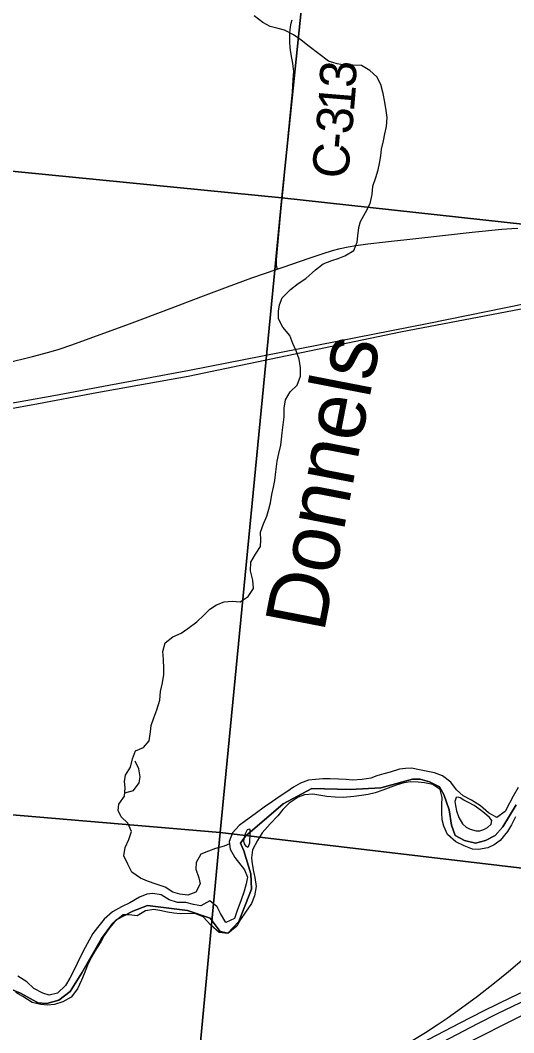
# Model space of a CAD drawing. Extents: x 831 to 1552, y 430 to 870.
# Drawn here: x 1297.11 to 1312.57, y 678.59 to 710.3 of the extents above; entities that cross this region are included whole.
import ezdxf

# ---------------------------------------------------------------- set-up
doc = ezdxf.new("R2010")
doc.units = 0
for name, color, linetype in [('GM_X_Corporation', 7, 'Continuous'), ('GM_X_County_Road', 7, 'Continuous'), ('GM_X_County_Road_Text', 7, 'Continuous'), ('GM_X_Interchange_Ramps', 7, 'Continuous'), ('GM_X_Interstate_Route', 7, 'Continuous'), ('GM_X_Major_River', 7, 'Continuous'), ('GM_X_Minor_River', 7, 'Continuous'), ('GM_X_Minor_River_Text', 7, 'Continuous'), ('GM_X_Rail_Line', 7, 'Continuous')]:
    doc.layers.add(name, color=color, linetype=linetype)

msp = doc.modelspace()

# ---------------------------------------------------------------- linework, layer by layer
at = {"layer": 'GM_X_Corporation'}
for points in [[(1287.469, 726.554), (1307.365, 724.655), (1305.299, 704.746), (1285.616, 706.68)], [(1307.365, 724.655), (1327.468, 722.912), (1325.539, 702.531), (1305.299, 704.746)], [(1305.299, 704.746), (1303.37, 684.858), (1283.584, 686.544), (1285.616, 706.68)], [(1305.299, 704.746), (1325.539, 702.531), (1323.531, 682.478), (1303.37, 684.858)], [(1283.584, 686.544), (1303.37, 684.858), (1301.464, 664.502), (1281.807, 666.237)], [(1303.37, 684.858), (1323.531, 682.478), (1321.541, 662.548), (1301.887, 664.457), (1301.464, 664.502)]]:
    msp.add_lwpolyline(points, close=True, dxfattribs=at)
for points in [[(1312.65, 685.727), (1312.224, 685.034), (1311.984, 684.768), (1311.69, 684.608), (1311.37, 684.528), (1311.023, 684.608), (1310.73, 684.768), (1310.623, 685.088), (1310.543, 685.568), (1310.383, 686.048), (1310.249, 686.288), (1309.929, 686.448), (1309.636, 686.528), (1309.396, 686.528), (1308.409, 686.262), (1307.449, 686.208), (1306.248, 686.235), (1305.341, 685.755), (1304.168, 684.742), (1304.007, 684.529), (1304.114, 684.289), (1304.328, 683.569), (1304.355, 683.089), (1303.954, 682.076), (1303.608, 681.702), (1303.368, 681.756), (1303.055, 682.179), (1302.347, 682.415), (1301.098, 682.568), (1300.638, 682.393), (1300.108, 682.128), (1300.004, 682.019), (1299.652, 681.539), (1299.039, 680.465), (1298.667, 679.874), (1298.316, 679.611), (1297.944, 679.502), (1297.659, 679.524), (1297.63, 679.54), (1297.111, 679.83), (1295.709, 680.4)], [(1295.709, 680.4), (1297.111, 679.83), (1297.63, 679.54), (1297.659, 679.524), (1297.944, 679.502), (1298.316, 679.611), (1298.667, 679.874), (1299.039, 680.465), (1299.652, 681.539), (1300.004, 682.019), (1300.108, 682.128), (1300.638, 682.393), (1301.098, 682.568), (1302.347, 682.415), (1303.055, 682.179), (1303.368, 681.756), (1303.608, 681.702), (1303.954, 682.076), (1304.355, 683.089), (1304.328, 683.569), (1304.114, 684.289), (1304.007, 684.529), (1304.168, 684.742), (1305.341, 685.755), (1306.248, 686.235), (1307.449, 686.208), (1308.409, 686.262), (1309.396, 686.528), (1309.636, 686.528), (1309.929, 686.448), (1310.249, 686.288), (1310.383, 686.048), (1310.543, 685.568), (1310.623, 685.088), (1310.73, 684.768), (1311.023, 684.608), (1311.37, 684.528), (1311.69, 684.608), (1311.984, 684.768), (1312.224, 685.034), (1312.65, 685.727)]]:
    msp.add_lwpolyline(points, dxfattribs=at)
at = {"layer": 'GM_X_County_Road'}
for points in [[(1305.159, 702.509), (1305.153, 702.543), (1305.138, 702.632), (1305.135, 702.671), (1305.141, 702.802), (1305.287, 704.41), (1305.365, 705.213), (1305.452, 706.14), (1305.636, 708.057), (1305.664, 708.429), (1305.673, 708.586), (1305.675, 708.711), (1305.671, 708.776), (1305.663, 708.854), (1305.648, 708.961), (1305.622, 709.114), (1305.59, 709.299), (1305.57, 709.448), (1305.557, 709.617), (1305.55, 709.768), (1305.551, 709.907), (1305.56, 709.992), (1305.577, 710.102), (1305.6, 710.211), (1305.625, 710.32)], [(1305.159, 702.509), (1305.345, 702.573), (1306.163, 702.854), (1306.596, 702.998), (1306.894, 703.089), (1307.135, 703.153), (1307.379, 703.207), (1307.625, 703.249), (1307.994, 703.3), (1308.55, 703.366), (1309.601, 703.482), (1311.27, 703.663), (1312.198, 703.759), (1312.508, 703.784), (1312.696, 703.791)], [(1292.633, 698.634), (1292.832, 698.659), (1293.002, 698.688), (1293.111, 698.71), (1293.836, 698.882), (1294.929, 699.15), (1295.727, 699.34), (1296.648, 699.564), (1297.492, 699.772), (1298.005, 699.907), (1298.324, 700.001), (1298.721, 700.132), (1300.531, 700.794), (1301.831, 701.285), (1302.769, 701.643), (1303.599, 701.948), (1304.36, 702.232), (1305.159, 702.509)]]:
    msp.add_lwpolyline(points, dxfattribs=at)
at = {"layer": 'GM_X_Interchange_Ramps'}
msp.add_lwpolyline([(1316.766, 684.819), (1316.253, 684.266), (1315.369, 683.31), (1314.816, 682.723), (1314.381, 682.282), (1313.979, 681.895), (1313.477, 681.432), (1312.968, 680.979), (1312.401, 680.496), (1311.97, 680.143), (1311.432, 679.723), (1310.935, 679.352), (1310.48, 679.028), (1310.172, 678.821), (1309.805, 678.588), (1309.008, 678.109), (1307.562, 677.263), (1306.957, 676.925), (1306.87, 676.872), (1306.781, 676.807), (1306.736, 676.769), (1306.693, 676.73), (1306.652, 676.687), (1306.577, 676.607)], dxfattribs=at)
at = {"layer": 'GM_X_Interstate_Route'}
for points in [[(1296.221, 671.1), (1298.795, 672.482), (1301.269, 673.783), (1303.737, 675.096), (1306.577, 676.607), (1306.973, 676.818), (1309.934, 678.396), (1310.869, 678.886), (1311.642, 679.283), (1312.478, 679.693), (1313.096, 679.984), (1313.775, 680.291), (1314.453, 680.589), (1314.514, 680.616), (1315.029, 680.832), (1315.72, 681.109), (1316.416, 681.372), (1317.469, 681.748), (1318.641, 682.161), (1319.931, 682.613), (1320.991, 682.995), (1322.52, 683.559), (1323.315, 683.849), (1323.468, 683.902)], [(1308.905, 677.534), (1309.028, 677.6), (1310.125, 678.184), (1311.445, 678.879), (1312.057, 679.186), (1312.786, 679.534), (1313.002, 679.632)]]:
    msp.add_lwpolyline(points, dxfattribs=at)
at = {"layer": 'GM_X_Major_River'}
for points in [[(1312.709, 686.272), (1312.551, 685.994), (1312.44, 685.776), (1312.305, 685.52), (1312.042, 685.329), (1311.779, 685.479), (1311.525, 685.69), (1311.247, 685.871), (1310.984, 686.006), (1310.776, 686.193), (1310.598, 686.433), (1310.337, 686.637), (1310.088, 686.733), (1309.83, 686.777), (1309.618, 686.827), (1309.368, 686.871), (1309.178, 686.86), (1308.987, 686.842), (1308.696, 686.749), (1308.497, 686.693), (1308.283, 686.637), (1308.091, 686.565), (1307.816, 686.518), (1307.519, 686.494), (1307.322, 686.521), (1307.079, 686.526), (1306.82, 686.54), (1306.584, 686.537), (1306.363, 686.519), (1306.135, 686.494), (1305.889, 686.401), (1305.666, 686.276), (1305.465, 686.136), (1305.218, 685.974), (1305.009, 685.834), (1304.747, 685.658), (1304.468, 685.443), (1304.166, 685.229), (1303.965, 685.082), (1303.762, 684.85), (1303.657, 684.579), (1303.682, 684.335), (1303.836, 684.081), (1304.132, 683.694), (1304.225, 683.456), (1304.19, 683.251), (1304.124, 683.017), (1304.018, 682.715), (1303.905, 682.421), (1303.816, 682.164), (1303.547, 682.041), (1303.386, 682.326), (1303.277, 682.534), (1303.045, 682.721), (1302.767, 682.56), (1302.54, 682.603)], [(1312.628, 685.353), (1312.5, 685.098), (1312.374, 684.888), (1312.147, 684.611), (1311.954, 684.471), (1311.754, 684.377), (1311.464, 684.33), (1311.274, 684.342), (1311.017, 684.439), (1310.754, 684.566), (1310.493, 684.8), (1310.377, 685.061), (1310.328, 685.253), (1310.318, 685.489), (1310.316, 685.732), (1310.329, 685.952), (1310.266, 686.205), (1310.034, 686.362), (1309.776, 686.413), (1309.579, 686.44), (1309.336, 686.446), (1309.13, 686.412), (1308.916, 686.356), (1308.716, 686.285), (1308.47, 686.184), (1308.225, 686.098), (1308.011, 686.049), (1307.805, 686.016), (1307.561, 685.991), (1307.241, 685.952), (1306.975, 685.966), (1306.716, 685.987), (1306.527, 686.014), (1306.277, 686.057), (1306.01, 686.04), (1305.811, 685.969), (1305.533, 685.777), (1305.338, 685.576), (1305.174, 685.382), (1304.94, 685.129), (1304.683, 684.845), (1304.54, 684.605), (1304.389, 684.312), (1304.353, 684.069), (1304.372, 683.879), (1304.412, 683.642), (1304.453, 683.451), (1304.5, 683.168)], [(1311.597, 685.506), (1311.477, 685.6), (1311.328, 685.709), (1311.155, 685.797), (1311.004, 685.876), (1310.892, 685.947), (1310.824, 685.964), (1310.763, 685.958), (1310.722, 685.829), (1310.742, 685.707), (1310.776, 685.539), (1310.847, 685.325), (1310.965, 685.132), (1311.084, 685.023), (1311.204, 684.967), (1311.393, 684.917), (1311.507, 684.907), (1311.638, 684.957), (1311.753, 685.015), (1311.862, 685.12), (1311.887, 685.233), (1311.813, 685.326), (1311.731, 685.404)], [(1311.731, 685.404), (1311.597, 685.506)], [(1304.29, 684.968), (1304.221, 684.947), (1304.165, 684.841), (1304.124, 684.705), (1304.099, 684.599), (1304.127, 684.508), (1304.171, 684.431), (1304.239, 684.399), (1304.262, 684.421), (1304.303, 684.534), (1304.305, 684.641), (1304.308, 684.747), (1304.309, 684.823)], [(1304.309, 684.823), (1304.316, 684.956), (1304.29, 684.968)], [(1304.5, 683.168), (1304.448, 682.873), (1304.351, 682.632), (1304.163, 682.362), (1304.013, 682.137), (1303.894, 681.927), (1303.608, 681.697), (1303.342, 681.726), (1303.081, 681.952), (1302.843, 682.216), (1302.61, 682.313), (1302.412, 682.325), (1302.115, 682.316), (1301.918, 682.328), (1301.721, 682.363), (1301.479, 682.421), (1301.289, 682.448), (1301.03, 682.408), (1300.775, 682.246), (1300.525, 682.282), (1300.327, 682.279), (1300.071, 682.072), (1299.907, 681.878), (1299.735, 681.638), (1299.631, 681.435), (1299.442, 681.143), (1299.331, 680.94), (1299.219, 680.699), (1299.114, 680.435), (1299.026, 680.231), (1298.906, 679.96), (1298.702, 679.699), (1298.44, 679.56), (1298.18, 679.474), (1297.959, 679.456), (1297.754, 679.476), (1297.481, 679.535), (1297.189, 679.724), (1296.971, 679.843)], [(1302.54, 682.603), (1302.291, 682.662), (1302.032, 682.668), (1301.775, 682.749), (1301.52, 682.907), (1301.263, 682.951), (1301.072, 682.932), (1300.842, 682.838), (1300.541, 682.655), (1300.279, 682.531), (1299.994, 682.37), (1299.738, 682.14), (1299.527, 681.886), (1299.378, 681.692), (1299.267, 681.489), (1299.14, 681.256), (1298.989, 680.955), (1298.893, 680.752), (1298.774, 680.511), (1298.662, 680.293), (1298.528, 680.067), (1298.279, 679.829), (1298.011, 679.759), (1297.815, 679.824), (1297.537, 679.975), (1297.313, 680.178), (1297.028, 680.359)]]:
    msp.add_lwpolyline(points, dxfattribs=at)
at = {"layer": 'GM_X_Minor_River'}
for points in [[(1306.356, 702.488), (1306.594, 702.675), (1306.869, 702.778), (1307.067, 702.837), (1307.281, 702.925), (1307.556, 703.089), (1307.666, 703.353), (1307.683, 703.551), (1307.717, 703.808), (1307.765, 704.005), (1307.928, 704.277), (1308.076, 704.563), (1308.132, 704.844), (1308.158, 705.102), (1308.253, 705.381), (1308.317, 705.616), (1308.365, 705.813), (1308.406, 706.055), (1308.431, 706.268), (1308.488, 706.525), (1308.536, 706.745), (1308.584, 706.98), (1308.603, 707.26), (1308.575, 707.481), (1308.533, 707.74), (1308.475, 708.006), (1308.403, 708.295), (1308.277, 708.532), (1308.059, 708.725), (1307.795, 708.887), (1307.529, 708.898), (1307.263, 708.894), (1307.036, 708.942), (1306.771, 709.021), (1306.462, 709.253), (1306.161, 709.484), (1305.913, 709.684), (1305.672, 709.847), (1305.385, 709.995), (1305.188, 710.042), (1304.938, 710.106), (1304.704, 710.23), (1304.441, 710.446)], [(1303.665, 684.507), (1303.497, 684.428), (1303.223, 684.356), (1303.009, 684.275), (1302.765, 684.179), (1302.617, 683.915), (1302.614, 683.71), (1302.702, 683.443), (1302.746, 683.253), (1302.613, 682.988), (1302.361, 682.893), (1302.111, 682.926), (1301.891, 682.989), (1301.65, 683.152), (1301.37, 683.246), (1301.09, 683.333), (1300.871, 683.427), (1300.6, 683.612), (1300.482, 683.872), (1300.356, 684.131), (1300.397, 684.389), (1300.506, 684.638), (1300.593, 684.888), (1300.482, 685.147), (1300.272, 685.355), (1300.176, 685.546), (1300.193, 685.751), (1300.379, 685.999), (1300.397, 686.257), (1300.377, 686.462), (1300.402, 686.652), (1300.557, 686.908), (1300.621, 687.165), (1300.715, 687.415), (1300.967, 687.518), (1301.152, 687.736), (1301.186, 688.017), (1301.211, 688.214), (1301.29, 688.448), (1301.392, 688.705), (1301.479, 689), (1301.505, 689.273), (1301.562, 689.546), (1301.603, 689.804), (1301.605, 689.994), (1301.601, 690.275), (1301.574, 690.533), (1301.646, 690.798), (1301.891, 690.992), (1302.151, 691.103), (1302.358, 691.245), (1302.642, 691.454), (1302.864, 691.664), (1303.049, 691.859), (1303.256, 691.994), (1303.493, 692.082), (1303.751, 692.102), (1303.994, 692.084), (1304.254, 692.255), (1304.417, 692.504), (1304.397, 692.762), (1304.317, 693.052), (1304.328, 693.325), (1304.483, 693.574), (1304.631, 693.815), (1304.641, 694.02), (1304.636, 694.27), (1304.731, 694.527), (1304.832, 694.769), (1304.896, 694.989), (1304.944, 695.185), (1304.993, 695.451), (1305.041, 695.678), (1305.082, 695.882), (1305.115, 696.155), (1305.157, 696.489), (1305.214, 696.731), (1305.27, 696.989), (1305.295, 697.186), (1305.313, 697.383), (1305.346, 697.633), (1305.372, 697.883), (1305.376, 698.157), (1305.417, 698.414), (1305.564, 698.663), (1305.787, 698.873), (1305.889, 699.153), (1305.893, 699.419), (1305.843, 699.685), (1305.755, 699.944), (1305.644, 700.173), (1305.556, 700.425), (1305.331, 700.686), (1305.197, 700.946), (1305.2, 701.196), (1305.233, 701.385), (1305.319, 701.605), (1305.573, 701.867), (1305.811, 702.054), (1306.056, 702.218), (1306.356, 702.488)], [(1300.386, 686.102), (1300.654, 686.178), (1300.832, 686.411), (1300.865, 686.601), (1300.822, 686.852), (1300.711, 687.096)]]:
    msp.add_lwpolyline(points, dxfattribs=at)
at = {"layer": 'GM_X_Rail_Line'}
for points in [[(1250.766, 679.957), (1255.444, 683.813), (1257.495, 685.358), (1259.895, 687.02), (1261.608, 688.118), (1265.466, 690.461), (1268.571, 692.318), (1270.198, 693.26), (1277.176, 696.209), (1284.864, 698.305), (1290.582, 698.552), (1291.934, 698.299), (1293.404, 698.016), (1295.482, 697.897), (1297.508, 698.271), (1299.512, 698.644), (1302.371, 699.157), (1309.027, 700.546), (1335.38, 705.567), (1347.114, 707.619), (1348.184, 707.837)], [(1347.068, 707.913), (1345.209, 707.623), (1335.331, 705.755), (1325.651, 703.882), (1316.479, 702.146), (1309.906, 700.809), (1302.408, 699.333), (1299.88, 698.86), (1298.165, 698.538), (1295.52, 698.073)], [(1261.527, 652.567), (1284.1, 664.037), (1310.179, 677.801), (1313.677, 679.557), (1320.635, 683.299), (1323.83, 685.434), (1326.948, 687.535)]]:
    msp.add_lwpolyline(points, dxfattribs=at)

# ---------------------------------------------------------------- texts
at = {"layer": 'GM_X_County_Road_Text'}
for s, rotation, p in [('3', 88.2328, (1307.621, 708.176)), ('1', 85.242, (1307.56, 707.414)), ('3', 84.9225, (1307.497, 706.71)), ('-', 84.8298, (1307.455, 706.243)), ('C', 84.8098, (1307.37, 705.313))]:
    msp.add_text(s, height=1.136, rotation=rotation, dxfattribs=at).set_placement(p)
at = {"layer": 'GM_X_Minor_River_Text'}
msp.add_text('Donnels', height=1.8933, rotation=78.9998, dxfattribs=at).set_placement((1306.62, 691.092))

doc.saveas('drawing.dxf')
